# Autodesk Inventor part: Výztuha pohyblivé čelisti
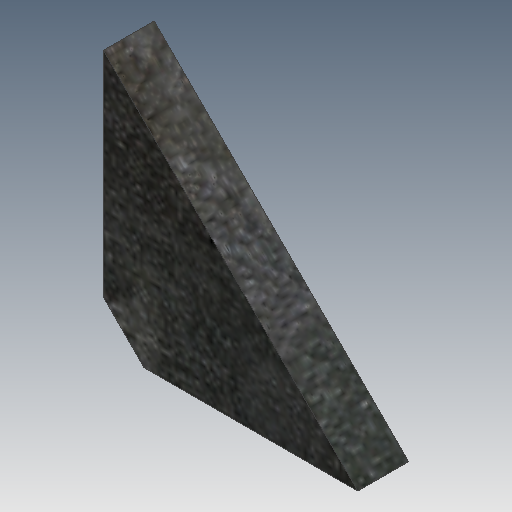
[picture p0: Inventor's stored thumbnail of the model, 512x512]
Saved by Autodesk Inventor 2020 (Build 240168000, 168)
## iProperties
Created: 2025-03
Part Number: Výztuha pohyblivé čelisti
Material: Ocel
Document SubType Name: Modeling
Designer: doma
Density: 7.85 g/cm^3
Appearance: Plech
Mass: 95.613 g
Surface Area: 40.9624 cm^2
Volume: 12.18 cm^3
Author: doma
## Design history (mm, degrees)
sketch "Náčrt1"
  geometry: L1 (0, 0)-(0, 50); L2 (0, 0)-(50, 0); L3 (50, 0)-(0, 50)
  constraints: 6 end point, 1 horizontal, 1 vertical
  dimensions: "d0" = 50 distance of L1.start L1.end; "d1" = 50 distance of L1.start L2.end
extrude "Vysunutí1" new body sketch "Náčrt1" distance "d2" = 10; taper "d3" = 0 deg
chamfer "Zkosení1" distance "d4" = 8; stored, may be unused: second distance "d5" = 2, angle "d6" = 45 deg
node "Těleso1"
